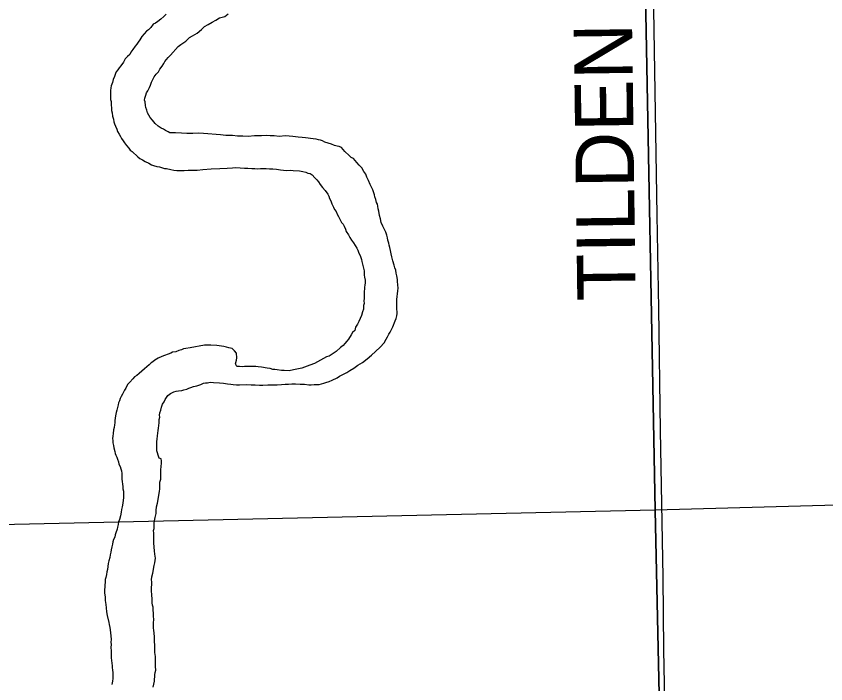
# Model space of a CAD drawing. Extents: x 10.6 to 44.6, y -2.6 to 23.4.
# Drawn here: x 16.643 to 17.431, y 16.432 to 17.081 of the extents above; entities that cross this region are included whole.
import ezdxf

# ---------------------------------------------------------------- set-up
doc = ezdxf.new("R2010")
doc.units = 0
for name, color, linetype in [('GM_X_Major_River', 7, 'Continuous'), ('GM_X_Section', 7, 'Continuous'), ('GM_X_Township_Road', 7, 'Continuous'), ('GM_X_Township_Road_Text', 7, 'Continuous')]:
    doc.layers.add(name, color=color, linetype=linetype)

msp = doc.modelspace()

# ---------------------------------------------------------------- linework, layer by layer
at = {"layer": 'GM_X_Major_River'}
for points in [[(16.78902, 17.08284), (16.78679, 17.08051), (16.7838, 17.07816), (16.78081, 17.07581), (16.77856, 17.07423), (16.77631, 17.07304), (16.77409, 17.06995), (16.77186, 17.06761), (16.76999, 17.06643), (16.76777, 17.06371), (16.76555, 17.061), (16.76334, 17.0579), (16.76187, 17.05559), (16.76039, 17.05365), (16.75891, 17.05172), (16.7567, 17.04862), (16.75486, 17.04591), (16.75377, 17.04361), (16.75153, 17.04166), (16.7493, 17.03932), (16.74747, 17.03624), (16.74488, 17.03275), (16.74341, 17.03081), (16.74193, 17.02888), (16.74045, 17.02694), (16.73974, 17.02502), (16.73865, 17.02234), (16.73758, 17.01927), (16.73688, 17.01659), (16.73544, 17.01313), (16.7351, 17.01122), (16.73478, 17.00855), (16.73486, 17.00513), (16.73493, 17.00208), (16.73499, 16.9998), (16.73541, 16.99791), (16.73545, 16.99601), (16.73549, 16.99411), (16.73592, 16.99221), (16.73599, 16.98917), (16.73642, 16.9869), (16.73687, 16.98386), (16.7377, 16.98084), (16.73814, 16.97819), (16.73895, 16.9763), (16.73976, 16.97404), (16.74097, 16.97102), (16.74178, 16.96875), (16.74336, 16.96613), (16.74456, 16.96387), (16.74574, 16.962), (16.74731, 16.95975), (16.7485, 16.95787), (16.75046, 16.95525), (16.75281, 16.95264), (16.75399, 16.95077), (16.75592, 16.94929), (16.76137, 16.94409), (16.76331, 16.94261), (16.766, 16.94115), (16.7687, 16.93969), (16.77217, 16.93786), (16.77486, 16.9364), (16.77678, 16.93568), (16.77985, 16.93461), (16.78252, 16.93429), (16.78443, 16.93395), (16.7875, 16.93288), (16.7894, 16.93293), (16.79361, 16.93188), (16.79667, 16.93119), (16.79934, 16.93087)], [(16.77852, 16.97644), (16.77577, 16.9798), (16.77343, 16.98241), (16.77224, 16.98467), (16.77105, 16.98692), (16.77022, 16.98957), (16.7694, 16.99221), (16.76898, 16.9941), (16.76852, 16.99752), (16.76809, 16.99941), (16.76843, 17.00132), (16.76913, 17.004), (16.76984, 17.0063), (16.77132, 17.00824), (16.77276, 17.0117), (16.77385, 17.014), (16.77493, 17.01669), (16.77565, 17.01861), (16.77747, 17.02208), (16.77932, 17.0244), (16.78155, 17.02674), (16.78301, 17.02943), (16.78523, 17.03215), (16.78669, 17.03484), (16.78779, 17.03677), (16.78927, 17.03871), (16.79113, 17.04065), (16.79335, 17.04299), (16.80077, 17.05152), (16.80339, 17.05349), (16.80826, 17.05664), (16.81161, 17.06014), (16.81461, 17.06173), (16.81912, 17.0645), (16.8236, 17.06802), (16.8262, 17.07075), (16.82996, 17.07274), (16.83371, 17.0751), (16.83748, 17.07709), (16.84085, 17.07945), (16.84614, 17.08071), (16.84951, 17.08307)], [(17.01365, 16.7938), (17.01361, 16.7957), (17.01355, 16.79836), (17.01347, 16.80179), (17.01343, 16.80369), (17.01338, 16.80559), (17.0137, 16.80826), (17.01402, 16.81093), (17.01433, 16.81398), (17.01465, 16.81665), (17.01458, 16.8197), (17.01413, 16.82311), (17.01408, 16.82501), (17.01362, 16.82842), (17.0128, 16.83107), (17.01235, 16.8341), (17.01154, 16.83637), (17.01072, 16.83901), (17.00948, 16.84317), (17.00863, 16.84696), (17.0078, 16.84998), (17.00735, 16.85302), (17.00652, 16.85604), (17.00609, 16.85832), (17.00567, 16.86021), (17.00484, 16.86324), (17.00441, 16.86551), (17.00358, 16.86815), (17.00276, 16.8708), (17.00156, 16.87343), (16.99996, 16.87682), (16.99836, 16.88021), (16.99751, 16.884), (16.99668, 16.88702), (16.99583, 16.89119), (16.99539, 16.89346), (16.99495, 16.89612), (16.99453, 16.89801), (16.99373, 16.89989), (16.9929, 16.90254), (16.99208, 16.90518), (16.99166, 16.90708), (16.99002, 16.91199), (16.98882, 16.91462), (16.98762, 16.91726), (16.98601, 16.92102), (16.98441, 16.92441), (16.9832, 16.92743), (16.98124, 16.93005), (16.97926, 16.93343), (16.97692, 16.93604), (16.97458, 16.93865), (16.97301, 16.94052), (16.97145, 16.94239), (16.96914, 16.94348), (16.9672, 16.94533), (16.96291, 16.94942), (16.95979, 16.95316), (16.95748, 16.95424), (16.95557, 16.95458), (16.95289, 16.95528), (16.94982, 16.95635), (16.94675, 16.95742), (16.9433, 16.95849), (16.94099, 16.95958), (16.93908, 16.9603), (16.93716, 16.96063), (16.93487, 16.96134), (16.9322, 16.96166), (16.92952, 16.96198), (16.92724, 16.96231), (16.92456, 16.96263), (16.92151, 16.96294), (16.91732, 16.96323), (16.91236, 16.96388), (16.90511, 16.96447), (16.89904, 16.96395), (16.89408, 16.9646), (16.89027, 16.96452), (16.88646, 16.96481), (16.8819, 16.9647), (16.87505, 16.96455), (16.86898, 16.96403), (16.86364, 16.96429), (16.85832, 16.96417), (16.85374, 16.96483), (16.84727, 16.96506), (16.84192, 16.9657), (16.82554, 16.96685), (16.8202, 16.96711), (16.81488, 16.96699), (16.80917, 16.96686), (16.80384, 16.96712), (16.79813, 16.96737), (16.79279, 16.96763), (16.79088, 16.96835), (16.78856, 16.96982), (16.78663, 16.97091), (16.78432, 16.972), (16.78124, 16.97384), (16.77852, 16.97644)], [(16.79934, 16.93087), (16.80314, 16.93095), (16.80657, 16.93103), (16.81037, 16.93112), (16.81379, 16.9312), (16.8157, 16.93124), (16.81912, 16.93132), (16.82481, 16.93183), (16.83279, 16.93239), (16.84115, 16.93296), (16.84838, 16.93312), (16.85369, 16.93362), (16.85673, 16.93369), (16.86093, 16.93341), (16.86512, 16.93312), (16.86854, 16.9332), (16.87235, 16.93291), (16.87539, 16.93298), (16.87769, 16.93265), (16.88073, 16.93272), (16.88377, 16.93278), (16.88643, 16.93284), (16.88948, 16.93253), (16.89291, 16.93261), (16.89634, 16.93231), (16.90016, 16.93163), (16.90321, 16.93132), (16.90626, 16.93101), (16.90968, 16.93109), (16.91274, 16.93078), (16.91883, 16.93054), (16.92189, 16.92984), (16.92495, 16.92915), (16.92687, 16.92844), (16.92916, 16.92811), (16.93109, 16.92663), (16.93382, 16.92365), (16.93577, 16.92179), (16.93734, 16.91992), (16.93891, 16.91729), (16.94127, 16.9143), (16.94362, 16.91131), (16.94636, 16.90795), (16.94716, 16.90607), (16.94798, 16.9038), (16.94917, 16.90154), (16.95038, 16.89853), (16.95198, 16.89514), (16.95279, 16.89288), (16.95436, 16.89101), (16.95556, 16.88837), (16.95675, 16.88611), (16.95795, 16.88348), (16.95955, 16.88047), (16.96111, 16.8786), (16.96229, 16.87673), (16.9635, 16.87371), (16.96432, 16.87145), (16.96629, 16.86845), (16.96787, 16.86582), (16.96945, 16.86319), (16.97141, 16.86057), (16.973, 16.85795), (16.97458, 16.85532), (16.97538, 16.85343), (16.97659, 16.85042), (16.97778, 16.84816), (16.97901, 16.84438), (16.97944, 16.84249), (16.98111, 16.83606), (16.98155, 16.83341), (16.9816, 16.83112), (16.98164, 16.82922), (16.98207, 16.82733), (16.98252, 16.8243), (16.98258, 16.82163), (16.98225, 16.81934), (16.98191, 16.81743), (16.98196, 16.81553), (16.98162, 16.81362), (16.9817, 16.8102), (16.98174, 16.8083), (16.98178, 16.80639), (16.98146, 16.8041), (16.98152, 16.80144), (16.98118, 16.79953), (16.98088, 16.7961), (16.98018, 16.79342), (16.97912, 16.78997), (16.97766, 16.78689), (16.97658, 16.7842), (16.97512, 16.78151), (16.97329, 16.77842), (16.9726, 16.77536), (16.97036, 16.77341), (16.96889, 16.77109), (16.96633, 16.76685), (16.96485, 16.76491), (16.963, 16.76259), (16.96114, 16.76064), (16.95852, 16.75868)], [(16.78393, 16.6398), (16.78423, 16.64323), (16.78454, 16.64628), (16.78449, 16.64857), (16.78406, 16.65046), (16.78214, 16.65118), (16.78131, 16.6542), (16.7805, 16.65647), (16.78008, 16.65836), (16.77991, 16.66559), (16.77987, 16.66749), (16.7802, 16.66978), (16.78051, 16.67283), (16.78083, 16.6755), (16.78115, 16.67817), (16.78147, 16.68046), (16.78179, 16.68313), (16.78212, 16.68542), (16.78242, 16.68885), (16.78275, 16.69115), (16.78271, 16.69305), (16.78304, 16.69534), (16.78374, 16.69802), (16.78444, 16.7007), (16.78551, 16.70377), (16.78698, 16.70608), (16.78807, 16.70839), (16.78954, 16.71033), (16.79064, 16.71225), (16.79326, 16.71421), (16.79665, 16.71581), (16.79892, 16.71625), (16.80119, 16.71668), (16.80423, 16.71713), (16.80612, 16.71755), (16.80915, 16.71838), (16.81103, 16.71919), (16.81291, 16.71999), (16.81556, 16.72081), (16.81896, 16.72165), (16.82274, 16.72288), (16.82538, 16.72408), (16.82727, 16.7245), (16.82917, 16.72454), (16.83182, 16.72499), (16.83526, 16.72468), (16.84097, 16.72443), (16.84478, 16.72414), (16.8486, 16.72346), (16.85203, 16.72316), (16.85432, 16.72283), (16.85738, 16.72252), (16.86042, 16.72259), (16.86764, 16.72275), (16.87183, 16.72247), (16.87564, 16.72256), (16.87983, 16.72227), (16.88325, 16.72235), (16.88782, 16.72245), (16.89276, 16.72256), (16.89694, 16.72266), (16.90113, 16.72275), (16.90492, 16.72322), (16.90796, 16.72329), (16.91138, 16.72337), (16.91481, 16.72344), (16.91938, 16.72317), (16.92356, 16.72326), (16.92777, 16.72259), (16.93005, 16.72265), (16.93309, 16.72272), (16.93803, 16.72283), (16.94257, 16.72407), (16.94445, 16.72488), (16.94748, 16.72571), (16.9505, 16.72692), (16.95539, 16.72931), (16.95764, 16.73088), (16.95951, 16.73207), (16.96215, 16.73327), (16.96478, 16.73447), (16.96778, 16.73644), (16.97153, 16.73881), (16.97566, 16.74157), (16.98016, 16.74433), (16.98464, 16.74786), (16.98875, 16.75138), (16.99285, 16.7549), (16.99732, 16.75918), (17.00103, 16.76345), (17.00323, 16.76693), (17.00432, 16.76924), (17.00578, 16.77193), (17.00688, 16.77386), (17.00835, 16.77618), (17.00943, 16.77886), (17.01196, 16.78463), (17.01267, 16.78693), (17.01337, 16.78961), (17.0137, 16.7919), (17.01365, 16.7938)], [(16.95852, 16.75868), (16.95443, 16.75478), (16.95067, 16.75242), (16.94768, 16.75045), (16.94503, 16.74962), (16.93338, 16.74327), (16.92885, 16.74165), (16.92093, 16.7388), (16.91298, 16.7371), (16.90881, 16.73624), (16.90386, 16.73651), (16.90119, 16.73645), (16.89699, 16.73712), (16.8947, 16.73745), (16.8928, 16.7374), (16.89011, 16.73848), (16.88744, 16.7388), (16.88553, 16.73914), (16.88362, 16.73948), (16.88171, 16.73981), (16.87866, 16.74013), (16.87637, 16.74045), (16.87333, 16.74039), (16.87066, 16.74033), (16.86724, 16.74025), (16.86534, 16.7402), (16.86344, 16.74016), (16.86039, 16.74047), (16.85773, 16.74041), (16.85652, 16.74305), (16.85759, 16.7465), (16.85791, 16.74879), (16.85743, 16.75334), (16.85548, 16.75558), (16.85314, 16.75781), (16.85008, 16.7585), (16.84778, 16.75921), (16.8451, 16.75991), (16.83823, 16.7609), (16.83252, 16.76115), (16.82834, 16.76106), (16.82643, 16.76101), (16.81241, 16.75841), (16.80824, 16.75794), (16.80597, 16.7575), (16.80408, 16.7567), (16.80144, 16.75588), (16.79842, 16.75467), (16.79539, 16.75422), (16.79351, 16.75341), (16.79087, 16.75221), (16.78747, 16.75099), (16.78483, 16.75017), (16.78144, 16.74857), (16.77806, 16.74659), (16.77619, 16.74503), (16.77432, 16.74385), (16.77246, 16.7419), (16.77022, 16.73995), (16.76799, 16.73799), (16.76537, 16.73565), (16.76276, 16.73369), (16.76052, 16.73174), (16.75827, 16.73016), (16.75679, 16.72823), (16.75382, 16.72512), (16.75159, 16.72278), (16.74977, 16.71932), (16.74867, 16.71739), (16.74757, 16.71546), (16.74647, 16.71353), (16.74538, 16.71123), (16.74429, 16.7093), (16.74358, 16.707), (16.74286, 16.70508), (16.74252, 16.70317), (16.74182, 16.70049), (16.74113, 16.69781), (16.74042, 16.69551), (16.73973, 16.69245), (16.7394, 16.69016), (16.73907, 16.68787), (16.73912, 16.68559), (16.73878, 16.68368), (16.73847, 16.68101), (16.73776, 16.67871), (16.73745, 16.67528), (16.73714, 16.6726), (16.73681, 16.67032), (16.73723, 16.66842), (16.73728, 16.66614), (16.73772, 16.66349), (16.73816, 16.66121), (16.739, 16.65781), (16.73942, 16.65591), (16.74022, 16.65403), (16.74103, 16.65215), (16.74183, 16.65026), (16.74265, 16.64762), (16.74309, 16.64534), (16.74428, 16.64309)], [(16.74428, 16.64309), (16.74509, 16.64082), (16.74552, 16.63893), (16.74596, 16.63628), (16.74602, 16.63361), (16.74608, 16.63095), (16.747, 16.62374), (16.74706, 16.62146), (16.74749, 16.61919), (16.74754, 16.61691), (16.74758, 16.615), (16.74764, 16.61272), (16.74731, 16.61043), (16.747, 16.60738), (16.74631, 16.60394), (16.74562, 16.60126), (16.7453, 16.59859), (16.74461, 16.59515), (16.74355, 16.5917), (16.74284, 16.5894), (16.74252, 16.58673), (16.74182, 16.58405), (16.74149, 16.58214), (16.74004, 16.57868), (16.73933, 16.57677), (16.739, 16.57447), (16.73791, 16.57217), (16.7372, 16.56987), (16.73687, 16.56758), (16.73617, 16.5649), (16.73547, 16.56222), (16.73514, 16.55993), (16.73445, 16.55725), (16.73413, 16.55458), (16.73343, 16.55152), (16.73274, 16.54884), (16.73242, 16.54579), (16.7321, 16.54312), (16.7314, 16.54082), (16.73108, 16.53814), (16.73038, 16.53509), (16.72967, 16.53317), (16.72973, 16.5305), (16.7294, 16.52821), (16.72945, 16.52631), (16.72914, 16.52288), (16.72921, 16.51984), (16.72967, 16.51642), (16.72975, 16.513), (16.73022, 16.50883), (16.73067, 16.50579), (16.73114, 16.502), (16.73161, 16.4982), (16.73329, 16.49139), (16.73371, 16.4895), (16.73416, 16.48647), (16.73459, 16.48419), (16.73503, 16.48154), (16.7351, 16.47849), (16.73556, 16.47508), (16.73524, 16.47241), (16.73567, 16.47014), (16.73536, 16.46709), (16.73543, 16.46404), (16.7355, 16.461), (16.73559, 16.4572), (16.73603, 16.45454), (16.73609, 16.45188), (16.73653, 16.44923), (16.73658, 16.44733), (16.737, 16.44543), (16.73707, 16.44239), (16.73714, 16.43935), (16.73719, 16.43707), (16.73687, 16.4344), (16.73618, 16.43134)], [(16.77658, 16.42845), (16.77758, 16.43456), (16.7782, 16.44066), (16.77853, 16.44295), (16.77886, 16.44524), (16.77878, 16.44866), (16.77874, 16.45057), (16.7787, 16.45247), (16.77863, 16.45513), (16.77856, 16.45855), (16.77809, 16.46235), (16.77802, 16.46539), (16.77792, 16.46958), (16.77785, 16.473), (16.77774, 16.47756), (16.77728, 16.48098), (16.77721, 16.48402), (16.77679, 16.48591), (16.77674, 16.48819), (16.77668, 16.49086), (16.77697, 16.49467), (16.77691, 16.49733), (16.77684, 16.50037), (16.77638, 16.50378), (16.77632, 16.50645), (16.7759, 16.50834), (16.77546, 16.51061), (16.77538, 16.51404), (16.77529, 16.51822), (16.77481, 16.5224), (16.77475, 16.52506), (16.77505, 16.52887), (16.77499, 16.53115), (16.77495, 16.53305), (16.77527, 16.53572), (16.77594, 16.53955), (16.7773, 16.54681), (16.778, 16.54949), (16.77833, 16.55177), (16.77866, 16.55407), (16.77819, 16.55786), (16.77773, 16.56127), (16.77727, 16.56469), (16.77717, 16.56887), (16.77706, 16.5742), (16.77696, 16.57838), (16.7769, 16.58104), (16.77724, 16.58295), (16.77756, 16.58562), (16.7775, 16.58791), (16.77783, 16.5902), (16.77851, 16.59364), (16.77919, 16.59746), (16.7795, 16.60051), (16.7798, 16.60394), (16.78048, 16.60738), (16.78115, 16.6112), (16.78182, 16.6154), (16.7825, 16.61884), (16.78282, 16.62151), (16.78275, 16.62456), (16.78306, 16.62799), (16.78375, 16.63067), (16.78404, 16.63486), (16.78398, 16.63752), (16.78393, 16.6398)]]:
    msp.add_lwpolyline(points, dxfattribs=at)
at = {"layer": 'GM_X_Section'}
for points in [[(17.2448, 17.67043), (18.18477, 17.67746), (18.20738, 16.62648), (17.26473, 16.60066)], [(17.2448, 17.67043), (17.26473, 16.60066), (16.29317, 16.57912), (16.26964, 17.66059)]]:
    msp.add_lwpolyline(points, close=True, dxfattribs=at)
for points in [[(18.22986, 15.52669), (18.20738, 16.62648), (17.26473, 16.60066), (17.28808, 15.52669)], [(17.28808, 15.52669), (17.26473, 16.60066), (16.29317, 16.57912), (16.31592, 15.52669)]]:
    msp.add_lwpolyline(points, dxfattribs=at)
at = {"layer": 'GM_X_Township_Road'}
msp.add_lwpolyline([(17.27227, 17.29478), (17.26732, 17.29387), (17.26415, 17.29122), (17.26203, 17.28831), (17.26097, 17.2854), (17.26018, 17.28064), (17.26097, 17.24305), (17.26271, 17.10779), (17.26626, 16.88735), (17.26812, 16.79657), (17.2697, 16.67827), (17.27209, 16.53562), (17.27288, 16.46495), (17.27659, 16.2826), (17.2787, 16.06717), (17.28055, 15.95416), (17.28188, 15.84777), (17.28347, 15.71967), (17.28558, 15.62889), (17.28606, 15.52669)], dxfattribs=at)

# ---------------------------------------------------------------- texts
at = {"layer": 'GM_X_Township_Road_Text'}
msp.add_text('TILDEN', height=0.056818, rotation=90.76096, dxfattribs=at).set_placement((17.24586, 16.80427))

doc.saveas('drawing.dxf')
